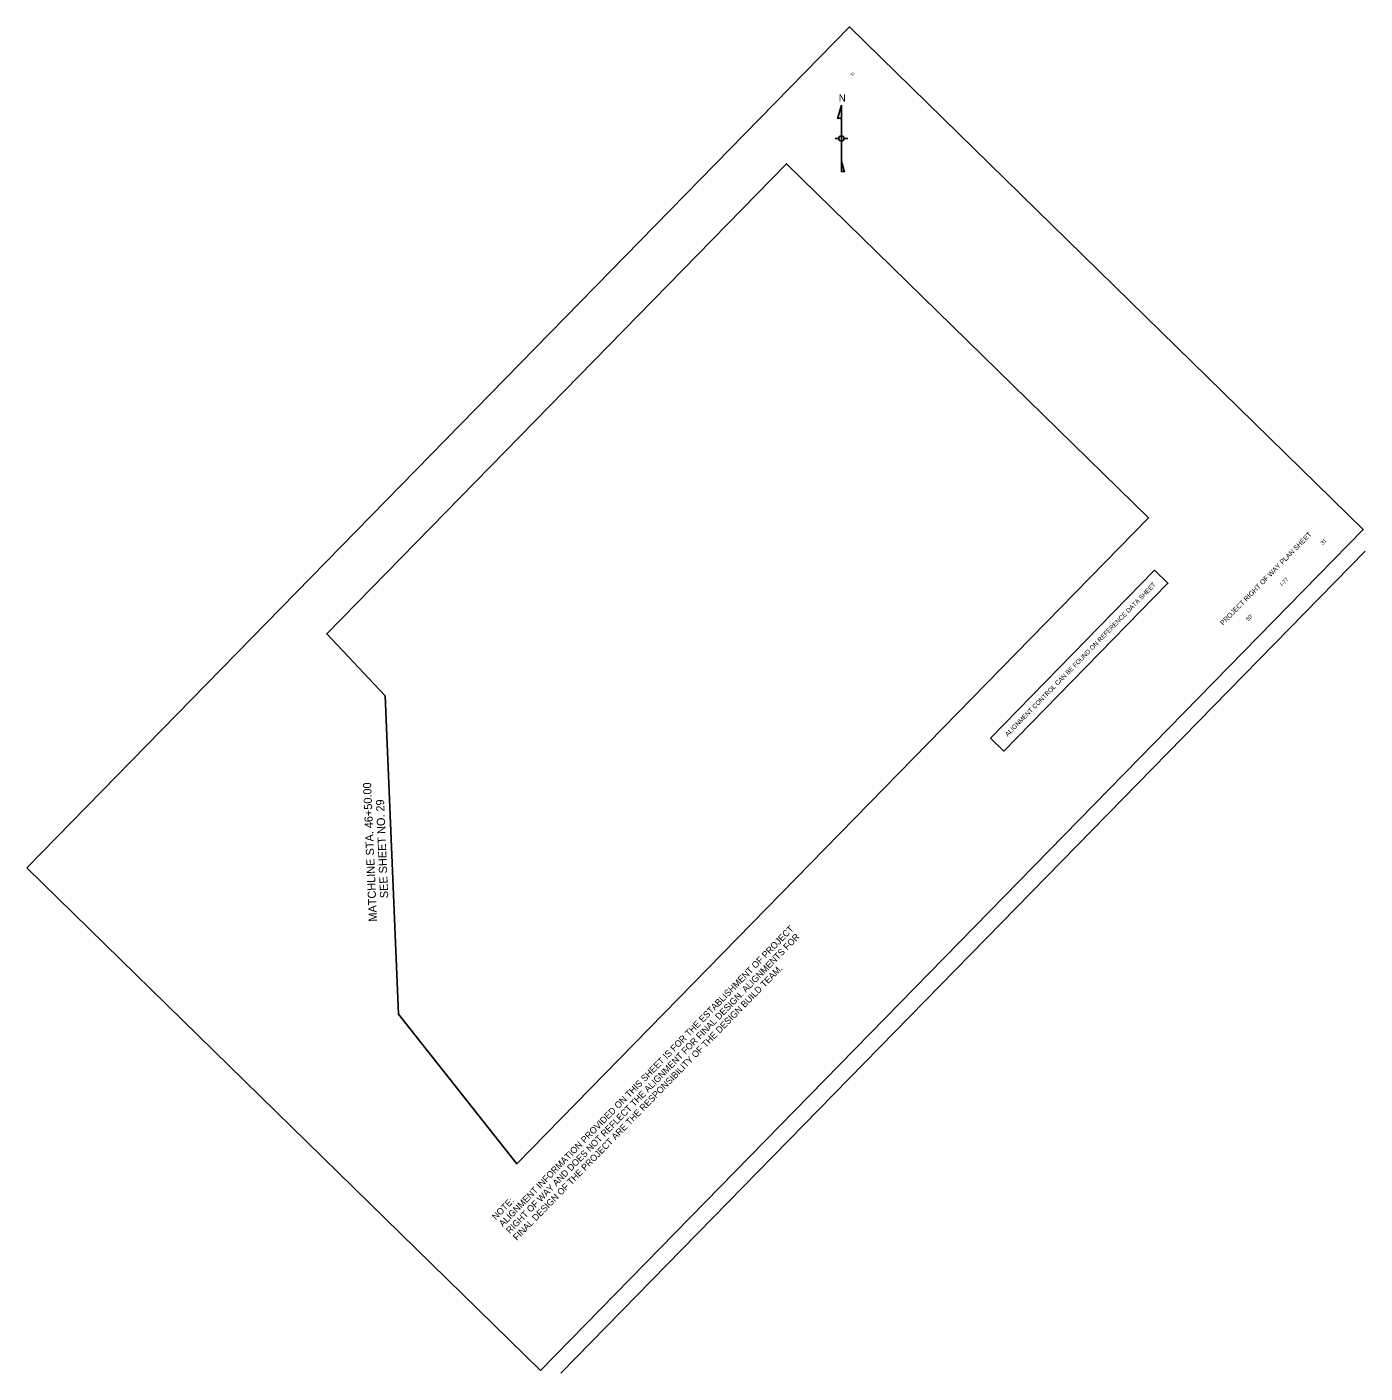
# Model space of a CAD drawing. Extents: x 2006416 to 2008464, y 1136491 to 1138551.
import ezdxf

# ---------------------------------------------------------------- set-up
doc = ezdxf.new("R2010")
doc.units = 0
for name, color, linetype in [('North Arrow', 7, 'Continuous'), ('RD_SHT_IplotShp', 7, 'Continuous'), ('RD_SHT_MatchLine', 7, 'Continuous'), ('RD_SHT_Misc1', 7, 'Continuous'), ('RD_SHT_ShtClip', 7, 'Continuous'), ('RD_SHT_TX', 7, 'Continuous')]:
    doc.layers.add(name, color=color, linetype=linetype)

msp = doc.modelspace()

# ---------------------------------------------------------------- linework, layer by layer
at = {"layer": 'North Arrow'}
for p, q in [((2007657, 1138410.5), (2007662.9, 1138431.6)), ((2007662.9, 1138431.6), (2007662.9, 1138409.4)), ((2007662.9, 1138431.6), (2007662.9, 1138329.3)), ((2007653.2, 1138380.4), (2007658.9, 1138380.4)), ((2007666.9, 1138380.4), (2007672.6, 1138380.4)), ((2007662.9, 1138345.2), (2007662.9, 1138329.3)), ((2007667.4, 1138329.1), (2007662.9, 1138345.2))]:
    msp.add_line(p, q, dxfattribs=at)
msp.add_circle((2007662.9, 1138380.4), 4.02, dxfattribs=at)
for centre, radius, start, end in [((2007659.6, 1138408), 3.59, 22.3707, 136.1387), ((2007665, 1138326.8), 3.3, 43.3397, 130.5607)]:
    msp.add_arc(centre, radius, start, end, dxfattribs=at)
at = {"layer": 'RD_SHT_IplotShp'}
msp.add_lwpolyline([(2006416.4, 1137264.5), (2007675.2, 1138551.1), (2008461.5, 1137781.9), (2007202.6, 1136495.2)], close=True, dxfattribs=at)
at = {"layer": 'RD_SHT_MatchLine'}
msp.add_line((2006985.3, 1137040.4), (2006964.4, 1137527.4), dxfattribs=at)
at = {"layer": 'RD_SHT_ShtClip'}
msp.add_lwpolyline([(2006964.4, 1137527.4), (2006875.3, 1137622.6), (2007578.9, 1138341.7), (2008132.9, 1137799.7), (2007166, 1136811.5), (2006985.3, 1137040.4)], close=True, dxfattribs=at)
at = {"layer": 'RD_SHT_TX'}
msp.add_line((2007233.5, 1136491.1), (2008464.4, 1137749.1), dxfattribs=at)
msp.add_lwpolyline([(2007891.1, 1137462.9), (2008142.3, 1137719.6), (2008162.5, 1137699.8), (2007911.4, 1137443)], close=True, dxfattribs=at)

# ---------------------------------------------------------------- texts
at = {"layer": 'North Arrow'}
msp.add_text('N', height=11.1, rotation=360, dxfattribs=at).set_placement((2007658.8, 1138437))
at = {"layer": 'RD_SHT_MatchLine'}
for s, p in [('MATCHLINE STA. 46+50.00', (2006952.2, 1137182.2)), ('SEE SHEET NO. 29', (2006969.4, 1137218))]:
    msp.add_text(s, height=12.5, rotation=92.4547, dxfattribs=at).set_placement(p)
at = {"layer": 'RD_SHT_Misc1'}
for s, p in [('ALIGNMENT INFORMATION PROVIDED ON THIS SHEET IS FOR THE ESTABLISHMENT OF PROJECT', (2007144.9, 1136714.2)), ('RIGHT OF WAY AND DOES NOT REFLECT THE ALIGNMENT FOR FINAL DESIGN. ALIGNMENTS FOR', (2007155.6, 1136703.7)), ('FINAL DESIGN OF THE PROJECT ARE THE RESPONSIBILITY OF THE DESIGN BUILD TEAM.', (2007166.3, 1136693.2)), ('NOTE:', (2007134.1, 1136724.6))]:
    msp.add_text(s, height=10, rotation=45.6253, dxfattribs=at).set_placement(p)
at = {"layer": 'RD_SHT_TX'}
for s, height, p in [('31', 4.5, (2007679.2, 1138475.2)), ('PROJECT RIGHT OF WAY PLAN SHEET', 7.5, (2008247.2, 1137634.9)), ('31', 6, (2008399.7, 1137758)), ('I-77', 6, (2008337.8, 1137694.8)), ('ALIGNMENT CONTROL CAN BE FOUND ON REFERENCE DATA SHEET', 7, (2007917.6, 1137464.7)), ("50'", 6, (2008285.5, 1137641.3))]:
    msp.add_text(s, height=height, rotation=45.6253, dxfattribs=at).set_placement(p)

doc.saveas('drawing.dxf')
